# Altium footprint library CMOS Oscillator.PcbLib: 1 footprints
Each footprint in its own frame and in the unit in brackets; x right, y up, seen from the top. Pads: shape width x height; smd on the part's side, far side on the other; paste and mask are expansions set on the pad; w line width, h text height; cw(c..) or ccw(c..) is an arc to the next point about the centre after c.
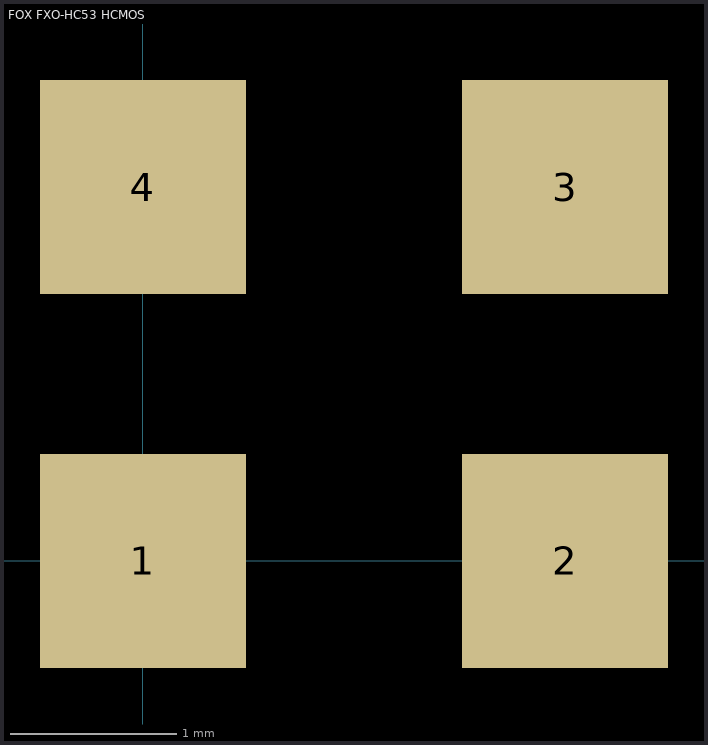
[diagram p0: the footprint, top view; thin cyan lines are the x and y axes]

## FOX FXO-HC53 HCMOS [mm]
pads (4):
  rect 1.24x1.29 smd: 1(0,0) 2(2.54,0) 3(2.54,2.25) 4(0,2.25)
